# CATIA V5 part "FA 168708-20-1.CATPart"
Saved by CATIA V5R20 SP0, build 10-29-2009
Part number: FA 168708-20-1
Revision: ANY
Definition: UNKNOWN
Nomenclature: FA 168708-20-1
Source: Unknown
Bounding box of the stored display mesh (mm): x -8 to 8, y 0.13 to 20.13, z -8 to 8
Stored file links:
  C:\Users\Utente\Desktop\IO LAVORO\3D X SITO CF\CUMSA\3D files FA\FA 168710-20\FA 168708-20-1.CATPart
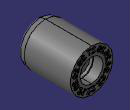
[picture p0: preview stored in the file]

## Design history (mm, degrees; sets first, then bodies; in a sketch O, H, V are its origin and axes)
Body1 "Cortar-Extruir4" (main body)
  Solid1: solid without history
